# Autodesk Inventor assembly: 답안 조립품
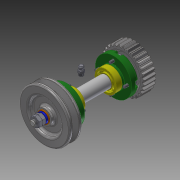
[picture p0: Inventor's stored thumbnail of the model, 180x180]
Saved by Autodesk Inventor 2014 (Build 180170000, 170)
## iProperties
Created: 2016-07
Part Number: 답안 조립품
Document SubType Name: Assembly
Designer: user
Author: user
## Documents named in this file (14)
- C:\Users\user\Desktop\460708V1005\답안 조립품.iam
- C:\Users\user\Desktop\460708V1005\본체.ipt
- C:\Users\user\Desktop\460708V1005\커버.ipt
- C:\Users\user\Desktop\460708V1005\볼트 M4 x 12.ipt
- C:\Users\user\Desktop\460708V1005\오일 실 15 25 7.ipt
- C:\Users\user\Desktop\460708V1005\니플 M 6 x 0.75.ipt
- C:\Users\user\Desktop\460708V1005\베어링 15 x 32 x 9.ipt
- C:\Users\user\Desktop\460708V1005\축.ipt
- C:\Users\user\Desktop\460708V1005\키 3 x 3 x 12.ipt
- C:\Users\user\Desktop\460708V1005\V벨트풀리.ipt
- C:\Users\user\Desktop\460708V1005\스퍼기어.ipt
- C:\Users\user\Desktop\460708V1005\와셔 8x17.ipt
- C:\Users\user\Desktop\460708V1005\스프링와셔 8.ipt
- C:\Users\user\Desktop\460708V1005\너트 M 8.ipt
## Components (11 placed, 3 different names)
1. KS B 2023 6002 - 15 x 32 x 9:1 — 각도:2
2. KS B 2023 6002 - 15 x 32 x 9:2 — 각도:1
3. V벨트풀리:1
4. ISO 4762 M4 x 12:1
5. ISO 4762 M4 x 12:3
6. ISO 4762 M4 x 12:4
7. ISO 4762 M4 x 12:5
8. ISO 4762 M4 x 12:2
9. ISO 4762 M4 x 12:6
10. ISO 4762 M4 x 12:7
11. ISO 4762 M4 x 12:8
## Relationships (2: Angle 2)
- 각도:1 [Angle]: KS B 2023 6002 - 15 x 32 x 9:2
- 각도:2 [Angle]: KS B 2023 6002 - 15 x 32 x 9:1
